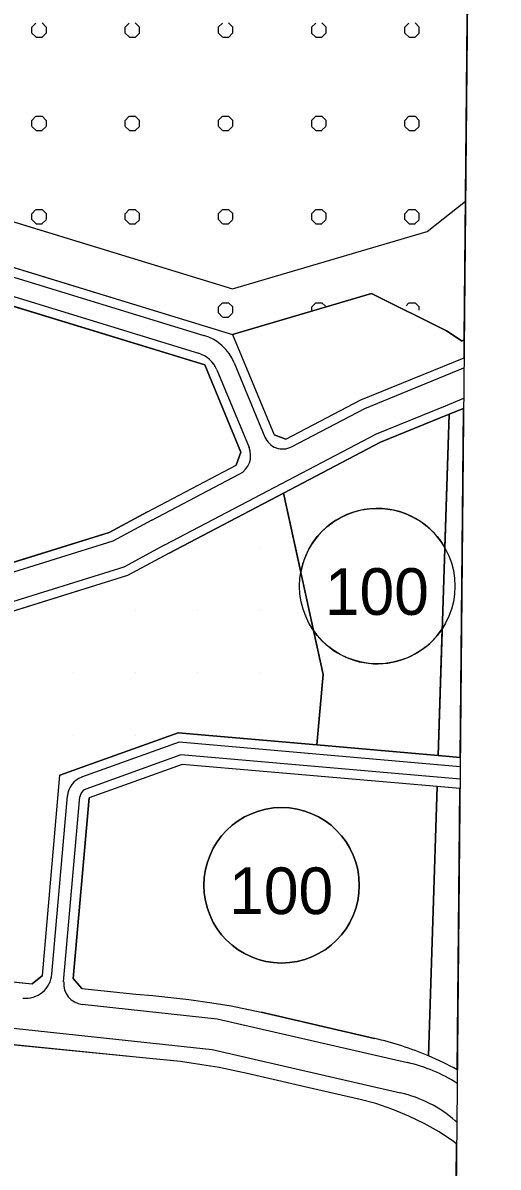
# Model space of a CAD drawing. Extents: x 427903 to 430077, y 4477233 to 4480385.
# Drawn here: x 429897.6 to 430050.5, y 4478600 to 4478968 of the extents above; entities that cross this region are included whole.
import ezdxf

# ---------------------------------------------------------------- set-up
doc = ezdxf.new("R2010")
doc.units = 0
for name, color, linetype in [('ADAKENARI', 7, 'Continuous'), ('KALDIRIM2', 7, 'Continuous'), ('PL_AYA_PARK_DINLENME', 7, 'Continuous'), ('PL_AYA_REKREASYON_AL', 7, 'Continuous'), ('PL_KA_TARIM_OZEL', 7, 'Continuous'), ('PL_KON_ONE_100', 7, 'Continuous'), ('PL_MESLEKI', 7, 'Continuous'), ('rezerv yapı alan', 7, 'Continuous'), ('SM_DAIRE', 7, 'Continuous'), ('SM_TAKS', 7, 'Continuous'), ('SıNıR', 7, 'Continuous'), ('TR_AZYOGUNKONUT', 7, 'Continuous'), ('TR_MESLEKTEKNİK', 7, 'Continuous'), ('TR_OZELMAHSUL', 7, 'Continuous')]:
    doc.layers.add(name, color=color, linetype=linetype)

msp = doc.modelspace()

# ---------------------------------------------------------------- linework, layer by layer
at = {"layer": 'ADAKENARI'}
for p, q in [((429779.96, 4478924.49), (429965.04, 4478867.84)), ((429778.16, 4478912.49), (429956.12, 4478858.02)), ((429965.04, 4478867.84), (430009.74, 4478881.03)), ((430009.74, 4478881.03), (430033.94, 4478869.02)), ((429965.04, 4478867.84), (429978.45, 4478835.49)), ((430033.94, 4478869.02), (430039, 4478865.62)), ((430039.62, 4478866.32), (430039, 4478865.62)), ((430006.33, 4478846.75), (430039.56, 4478860.29)), ((429956.12, 4478858.02), (429967.78, 4478829.9)), ((429982.26, 4478834.12), (430006.33, 4478846.75)), ((430034.72, 4478842.12), (430039.41, 4478844.03)), ((430012.66, 4478833.13), (430034.72, 4478842.12)), ((430034.72, 4478842.12), (430031.2, 4478732.4)), ((429982.26, 4478834.12), (429978.45, 4478835.49)), ((429981.49, 4478816.78), (430012.66, 4478833.13)), ((429967.78, 4478829.9), (429966.28, 4478825.73)), ((429937.68, 4478810.72), (429966.28, 4478825.73)), ((429944.72, 4478797.48), (429981.49, 4478816.78)), ((429994.21, 4478758.43), (429981.49, 4478816.78)), ((429937.68, 4478810.72), (429925.4, 4478804.12)), ((429925.4, 4478804.12), (429868.54, 4478786.43)), ((429944.71, 4478797.47), (429931.24, 4478790.23)), ((429931.24, 4478790.23), (429871.71, 4478771.71)), ((429994.21, 4478758.43), (429992.24, 4478735.79)), ((429947.54, 4478739.69), (429909.51, 4478726.04)), ((429992.24, 4478735.79), (429947.54, 4478739.69)), ((430031.2, 4478732.4), (429992.24, 4478735.79)), ((430038.34, 4478731.77), (430031.2, 4478732.4)), ((429903.89, 4478661.67), (429909.51, 4478726.04)), ((429948.86, 4478729.54), (429918.91, 4478718.79)), ((430030.88, 4478722.39), (429948.86, 4478729.54)), ((430030.88, 4478722.39), (430028.09, 4478635.77)), ((430038.24, 4478721.74), (430030.88, 4478722.39)), ((429913.85, 4478660.69), (429918.91, 4478718.79)), ((429810.6, 4478667.88), (429900.65, 4478658.98)), ((429903.89, 4478661.67), (429900.65, 4478658.98)), ((429916.57, 4478657.41), (429913.85, 4478660.69)), ((429916.57, 4478657.41), (429933.99, 4478655.68)), ((429933.99, 4478655.68), (429939.42, 4478655.15)), ((429939.42, 4478655.15), (429950.98, 4478653.96)), ((429950.98, 4478653.96), (429958.39, 4478652.85)), ((429958.39, 4478652.85), (429964.62, 4478651.87)), ((429964.62, 4478651.87), (429974.25, 4478649.82)), ((430010.75, 4478641.4), (429974.25, 4478649.82)), ((429937.24, 4478635.09), (429814.86, 4478647.18)), ((429948.29, 4478633.95), (429937.24, 4478635.09)), ((429955.17, 4478632.92), (429948.29, 4478633.95)), ((429960.8, 4478632.03), (429955.17, 4478632.92)), ((429969.74, 4478630.13), (429960.8, 4478632.03)), ((429992.56, 4478624.85), (429969.74, 4478630.13)), ((430006.15, 4478621.73), (429992.56, 4478624.85)), ((430011.13, 4478620.46), (430006.15, 4478621.73)), ((430016.67, 4478618.52), (430011.13, 4478620.46)), ((430021.78, 4478616.44), (430016.67, 4478618.52)), ((430026.71, 4478614.05), (430021.78, 4478616.44)), ((430031.6, 4478611.3), (430026.71, 4478614.05)), ((430036.22, 4478608.26), (430031.6, 4478611.3)), ((430037.15, 4478607.53), (430036.22, 4478608.26))]:
    msp.add_line(p, q, dxfattribs=at)
for start, end in [(67.0361, 77.0155), (61.3972, 67.0361)]:
    msp.add_arc((429987.2, 4478539.27), 104.81, start, end, dxfattribs=at)
at = {"layer": 'KALDIRIM2'}
for p, q in [((429790.01, 4478918.28), (429955.89, 4478867.5)), ((429788.25, 4478912.54), (429954.14, 4478861.76)), ((429965.58, 4478858.7), (429975.5, 4478834.79)), ((429960.03, 4478856.4), (429970.38, 4478831.48)), ((430007.6, 4478844.03), (430039.53, 4478857.04)), ((429984.08, 4478831.69), (430007.6, 4478844.03)), ((430011.4, 4478835.86), (430033.59, 4478844.9)), ((430033.59, 4478844.9), (430039.44, 4478847.28)), ((429978.73, 4478818.71), (430011.4, 4478835.86)), ((429939.09, 4478808.07), (429967.26, 4478822.86)), ((429943.32, 4478800.13), (429978.73, 4478818.71)), ((429939.09, 4478808.07), (429926.57, 4478801.34)), ((429926.57, 4478801.34), (429869.17, 4478783.49)), ((429943.29, 4478800.12), (429930.07, 4478793.01)), ((429930.07, 4478793.01), (429871.08, 4478774.65)), ((429947.94, 4478736.65), (429916.53, 4478725.37)), ((430038.31, 4478728.76), (429947.94, 4478736.65)), ((429948.47, 4478732.59), (429917.88, 4478721.61)), ((430038.27, 4478724.75), (429948.47, 4478732.59)), ((429906.94, 4478662.06), (429911.94, 4478719.42)), ((429910.74, 4478659.58), (429915.93, 4478719.07)), ((429816.04, 4478653.03), (429958.51, 4478637.85)), ((429816.04, 4478653.03), (429958.51, 4478637.85)), ((429916.69, 4478652.36), (429960.17, 4478647.73)), ((429960.17, 4478647.73), (430021.4, 4478633.61)), ((429958.51, 4478637.85), (430019.15, 4478623.87)), ((429958.51, 4478637.85), (430019.15, 4478623.87)), ((430037.22, 4478614.48), (430036.72, 4478614.91)), ((430037.22, 4478614.48), (430036.72, 4478614.91))]:
    msp.add_line(p, q, dxfattribs=at)
for centre, radius, start, end in [((429951.4, 4478852.82), 15.35, 22.5339, 72.9797), ((429951.4, 4478852.82), 9.35, 22.5339, 72.9797), ((429981.21, 4478837.16), 6.18, 202.5338, 297.6881), ((429964.1, 4478828.87), 6.8, 297.6881, 22.5338), ((429918.89, 4478718.81), 6.97, 109.747, 175.0148), ((429918.89, 4478718.81), 2.97, 109.747, 175.0148), ((429898.52, 4478662.8), 8.46, 263.9177, 355.0148), ((429917.4, 4478659), 6.68, 175.0148, 263.9177), ((430010.01, 4478584.22), 50.69, 57.3784, 77.019), ((430010.01, 4478584.22), 40.69, 48.9678, 77.019), ((430010.01, 4478584.22), 40.69, 48.9678, 77.019)]:
    msp.add_arc(centre, radius, start, end, dxfattribs=at)
at = {"layer": 'PL_AYA_PARK_DINLENME'}
for points in [[(430039.62, 4478866.32), (430039, 4478865.62), (430033.94, 4478869.02), (430009.74, 4478881.03), (429965.04, 4478867.84), (429978.45, 4478835.49), (429982.26, 4478834.12), (430006.33, 4478846.75), (430039.56, 4478860.29)], [(430039.56, 4478860.29), (430039.62, 4478866.32)], [(430039.41, 4478844.03), (430034.72, 4478842.12), (430031.2, 4478732.4), (430038.34, 4478731.77)], [(430038.34, 4478731.77), (430039.41, 4478844.03)], [(430038.24, 4478721.74), (430030.88, 4478722.39), (430028.09, 4478635.77)], [(430037.38, 4478631.29), (430038.24, 4478721.74)]]:
    msp.add_lwpolyline(points, dxfattribs=at)
msp.add_arc((429987.2, 4478539.27), 104.81, 61.3973, 67.0361, dxfattribs=at)
at = {"layer": 'PL_AYA_REKREASYON_AL'}
for points in [[(430037.15, 4478607.53), (430036.22, 4478608.26), (430031.6, 4478611.3), (430026.71, 4478614.05), (430021.78, 4478616.44), (430016.67, 4478618.52), (430011.13, 4478620.46), (430006.15, 4478621.73), (429992.56, 4478624.85), (429969.74, 4478630.13), (429960.8, 4478632.03), (429955.17, 4478632.92), (429948.29, 4478633.95), (429937.24, 4478635.09), (429814.86, 4478647.18), (429808.17, 4478641.82), (429802.69, 4478596.3)], [(430035.95, 4478482.02), (430037.15, 4478607.53)]]:
    msp.add_lwpolyline(points, dxfattribs=at)
at = {"layer": 'PL_KA_TARIM_OZEL'}
for points in [[(430039.62, 4478866.32), (430041.04, 4479015.36)], [(429185.17, 4478965.6), (429186.08, 4478965.07), (429221.81, 4478944.56), (429259.98, 4478922.84), (429299.06, 4478900.66), (429338.45, 4478878.32), (429344.42, 4478874.94), (429379.33, 4478881.11), (429380.15, 4478898.3), (429392.14, 4478897.73), (429391.78, 4478890.33), (429396.47, 4478886.21), (429613.09, 4478924.65), (429779.96, 4478924.49), (429965.04, 4478867.84), (430009.74, 4478881.03), (430033.94, 4478869.02), (430039, 4478865.62), (430039.62, 4478866.32)]]:
    msp.add_lwpolyline(points, dxfattribs=at)
at = {"layer": 'PL_KON_ONE_100'}
for points in [[(429703.83, 4478785.08), (429809.52, 4478788.03), (429859.15, 4478785.27), (429868.54, 4478786.43), (429925.4, 4478804.12), (429937.68, 4478810.72), (429966.28, 4478825.73), (429967.78, 4478829.9), (429956.12, 4478858.02), (429778.16, 4478912.49), (429642.39, 4478912.63)], [(430031.2, 4478732.4), (430034.72, 4478842.12), (430012.66, 4478833.13), (429981.49, 4478816.78), (429994.21, 4478758.43), (429992.24, 4478735.79), (430031.2, 4478732.4)], [(430028.09, 4478635.77), (430030.88, 4478722.39), (429948.86, 4478729.54), (429918.91, 4478718.79), (429913.85, 4478660.69), (429916.57, 4478657.41), (429933.99, 4478655.68), (429939.42, 4478655.15), (429950.98, 4478653.96), (429958.39, 4478652.85), (429964.62, 4478651.87), (429974.25, 4478649.82), (430010.75, 4478641.4)]]:
    msp.add_lwpolyline(points, dxfattribs=at)
msp.add_arc((429987.2, 4478539.27), 104.81, 67.0361, 77.0155, dxfattribs=at)
at = {"layer": 'PL_MESLEKI'}
msp.add_lwpolyline([(429991.12, 4478772.6), (429987.04, 4478791.33), (429981.49, 4478816.78), (429944.71, 4478797.47), (429931.24, 4478790.23), (429871.71, 4478771.71), (429859.66, 4478770.22), (429809.16, 4478773.03), (429741.71, 4478771.14), (429742.27, 4478751.03), (429673.79, 4478725.23), (429753.01, 4478675.43), (429790.96, 4478670.46), (429810.6, 4478667.88), (429900.65, 4478658.98), (429903.89, 4478661.67), (429909.51, 4478726.04), (429947.54, 4478739.69), (429992.24, 4478735.79), (429994.21, 4478758.43), (429991.12, 4478772.6)], dxfattribs=at)
at = {"layer": 'rezerv yapı alan'}
for p, q in [((429782.06, 4478938.49), (429965.11, 4478882.46)), ((430027.68, 4478900.91), (430040.04, 4478910.67)), ((429965.11, 4478882.46), (430027.68, 4478900.91))]:
    msp.add_line(p, q, dxfattribs=at)
for points in [[(430040.04, 4478910.67), (430050.52, 4480009.82), (427929.02, 4480028.95), (427921.98, 4479290.57)], [(427921.98, 4479290.57), (427971.55, 4479260.72), (427987.38, 4479256.4), (428128.47, 4479257.63), (428368.56, 4479183.35), (428552.54, 4479194.57), (428656.99, 4479201.54), (428694.28, 4479196.96), (428778.69, 4479177.41), (428853.9, 4479147.32), (428942.46, 4479108.55), (429057.71, 4479108.55), (429083.4, 4479100.66), (429102.93, 4479079.75), (429129.55, 4479022.57), (429151, 4479001.12), (429217.97, 4478963.3), (429343.9, 4478891.1), (429611.87, 4478938.66), (429782.06, 4478938.49), (429965.11, 4478882.46), (430027.68, 4478900.91), (430040.04, 4478910.67)]]:
    msp.add_lwpolyline(points, dxfattribs=at)
at = {"layer": 'SM_DAIRE'}
for centre in [(430011.64, 4478786.88), (429980.86, 4478690.64)]:
    msp.add_circle(centre, 25, dxfattribs=at)
at = {"layer": 'SıNıR'}
msp.add_line((430050.52, 4480009.82), (430024.04, 4477233.04), dxfattribs=at)
at = {"layer": 'TR_AZYOGUNKONUT'}
for points in [[(429956.12, 4478858.02), (429778.16, 4478912.49), (429642.39, 4478912.63), (429660.09, 4478771.16)], [(429703.83, 4478785.08), (429809.52, 4478788.03), (429859.15, 4478785.27), (429868.54, 4478786.43), (429925.4, 4478804.12), (429937.68, 4478810.72), (429966.28, 4478825.73), (429967.78, 4478829.9), (429956.12, 4478858.02)], [(430033.35, 4478799.29), (430034.72, 4478842.12), (430012.66, 4478833.13), (429981.49, 4478816.78), (429987.04, 4478791.33)], [(429991.12, 4478772.6), (429994.21, 4478758.43), (429992.24, 4478735.79), (430031.2, 4478732.4), (430032.5, 4478773.1)], [(430028.09, 4478635.77), (430030.88, 4478722.39), (429948.86, 4478729.54), (429918.91, 4478718.79), (429913.85, 4478660.69), (429916.57, 4478657.41), (429933.99, 4478655.68), (429939.42, 4478655.15), (429950.98, 4478653.96), (429958.39, 4478652.85), (429964.62, 4478651.87), (429974.25, 4478649.82), (430010.75, 4478641.4)]]:
    msp.add_lwpolyline(points, dxfattribs=at)
for centre, radius, start, end in [((430011.64, 4478786.88), 25, 29.7639, 169.754), ((430011.64, 4478786.88), 25, 214.8391, 326.5565), ((429980.86, 4478690.64), 25, 0, 180), ((429980.86, 4478690.64), 25, 180, 0), ((429987.2, 4478539.27), 104.81, 77.0149, 77.0155), ((429987.2, 4478539.27), 104.81, 67.0361, 77.015)]:
    msp.add_arc(centre, radius, start, end, dxfattribs=at)
at = {"layer": 'TR_MESLEKTEKNİK'}
for p, q in [((429953.79, 4478798.98), (429953.79, 4478798.98)), ((429973.79, 4478798.98), (429973.79, 4478798.98)), ((429933.79, 4478778.98), (429933.79, 4478778.98)), ((429953.79, 4478778.98), (429953.79, 4478778.98)), ((429973.79, 4478778.98), (429973.79, 4478778.98)), ((429913.79, 4478758.98), (429913.79, 4478758.98)), ((429933.79, 4478758.98), (429933.79, 4478758.98)), ((429953.79, 4478758.98), (429953.79, 4478758.98)), ((429973.79, 4478758.98), (429973.79, 4478758.98)), ((429913.79, 4478738.98), (429913.79, 4478738.98)), ((429933.79, 4478738.98), (429933.79, 4478738.98)), ((429973.79, 4478738.98), (429973.79, 4478738.98))]:
    msp.add_line(p, q, dxfattribs=at)
at = {"layer": 'TR_OZELMAHSUL'}
for p, q in [((429900.49, 4478966.62), (429901.84, 4478967.97)), ((429900.54, 4478964.75), (429900.54, 4478966.66)), ((429905.16, 4478966.66), (429903.8, 4478968.01)), ((429905.17, 4478964.75), (429905.17, 4478966.66)), ((429930.49, 4478966.62), (429931.84, 4478967.97)), ((429930.54, 4478964.75), (429930.54, 4478966.66)), ((429935.16, 4478966.66), (429933.8, 4478968.01)), ((429935.17, 4478964.75), (429935.17, 4478966.66)), ((429960.48, 4478966.62), (429961.84, 4478967.97)), ((429960.54, 4478964.75), (429960.54, 4478966.66)), ((429965.16, 4478966.66), (429963.8, 4478968.01)), ((429965.17, 4478964.75), (429965.17, 4478966.66)), ((429990.48, 4478966.62), (429991.84, 4478967.97)), ((429990.54, 4478964.75), (429990.54, 4478966.66)), ((429995.15, 4478966.66), (429993.8, 4478968.01)), ((429995.17, 4478964.75), (429995.17, 4478966.66)), ((430020.48, 4478966.62), (430021.84, 4478967.97)), ((430020.54, 4478964.75), (430020.54, 4478966.66)), ((430025.15, 4478966.66), (430023.8, 4478968.01)), ((430025.17, 4478964.75), (430025.17, 4478966.66)), ((429901.89, 4478963.39), (429900.53, 4478964.74)), ((429901.9, 4478963.39), (429903.82, 4478963.39)), ((429903.76, 4478963.35), (429905.11, 4478964.7)), ((429931.89, 4478963.39), (429930.53, 4478964.74)), ((429931.9, 4478963.39), (429933.82, 4478963.39)), ((429933.76, 4478963.35), (429935.11, 4478964.7)), ((429961.89, 4478963.39), (429960.53, 4478964.74)), ((429961.9, 4478963.39), (429963.82, 4478963.39)), ((429963.75, 4478963.35), (429965.11, 4478964.7)), ((429991.88, 4478963.39), (429990.53, 4478964.74)), ((429991.9, 4478963.39), (429993.82, 4478963.39)), ((429993.75, 4478963.35), (429995.11, 4478964.7)), ((430021.88, 4478963.39), (430020.53, 4478964.74)), ((430021.9, 4478963.39), (430023.82, 4478963.39)), ((430023.75, 4478963.35), (430025.11, 4478964.7)), ((429900.49, 4478936.62), (429901.84, 4478937.97)), ((429900.54, 4478934.75), (429900.54, 4478936.66)), ((429901.9, 4478938.02), (429903.82, 4478938.02)), ((429905.16, 4478936.66), (429903.8, 4478938.01)), ((429905.17, 4478934.75), (429905.17, 4478936.66)), ((429930.49, 4478936.62), (429931.84, 4478937.97)), ((429930.54, 4478934.75), (429930.54, 4478936.66)), ((429931.9, 4478938.02), (429933.82, 4478938.02)), ((429935.15, 4478936.66), (429933.8, 4478938.01)), ((429935.17, 4478934.75), (429935.17, 4478936.66)), ((429960.48, 4478936.62), (429961.84, 4478937.97)), ((429960.54, 4478934.75), (429960.54, 4478936.66)), ((429961.9, 4478938.02), (429963.82, 4478938.02)), ((429965.15, 4478936.66), (429963.8, 4478938.01)), ((429965.17, 4478934.75), (429965.17, 4478936.66)), ((429990.48, 4478936.62), (429991.84, 4478937.97)), ((429990.54, 4478934.75), (429990.54, 4478936.66)), ((429991.9, 4478938.02), (429993.82, 4478938.02)), ((429995.15, 4478936.66), (429993.8, 4478938.01)), ((429995.17, 4478934.75), (429995.17, 4478936.66)), ((430020.48, 4478936.62), (430021.84, 4478937.97)), ((430020.54, 4478934.75), (430020.54, 4478936.66)), ((430021.9, 4478938.02), (430023.82, 4478938.02)), ((430025.15, 4478936.66), (430023.8, 4478938.01)), ((430025.17, 4478934.75), (430025.17, 4478936.66)), ((429901.89, 4478933.39), (429900.53, 4478934.74)), ((429901.9, 4478933.39), (429903.82, 4478933.39)), ((429903.76, 4478933.35), (429905.11, 4478934.7)), ((429931.88, 4478933.39), (429930.53, 4478934.74)), ((429931.9, 4478933.39), (429933.82, 4478933.39)), ((429933.76, 4478933.35), (429935.11, 4478934.7)), ((429961.88, 4478933.39), (429960.53, 4478934.74)), ((429961.9, 4478933.39), (429963.82, 4478933.39)), ((429963.75, 4478933.35), (429965.11, 4478934.7)), ((429991.88, 4478933.39), (429990.53, 4478934.74)), ((429991.9, 4478933.39), (429993.82, 4478933.39)), ((429993.75, 4478933.35), (429995.11, 4478934.7)), ((430021.88, 4478933.39), (430020.53, 4478934.74)), ((430021.9, 4478933.39), (430023.82, 4478933.39)), ((430023.75, 4478933.35), (430025.11, 4478934.7)), ((429900.49, 4478906.62), (429901.84, 4478907.97)), ((429900.54, 4478904.75), (429900.54, 4478906.66)), ((429901.9, 4478908.02), (429903.82, 4478908.02)), ((429905.15, 4478906.66), (429903.8, 4478908.01)), ((429905.17, 4478904.75), (429905.17, 4478906.66)), ((429930.49, 4478906.62), (429931.84, 4478907.97)), ((429930.54, 4478904.75), (429930.54, 4478906.66)), ((429931.9, 4478908.02), (429933.82, 4478908.02)), ((429935.15, 4478906.66), (429933.8, 4478908.01)), ((429935.17, 4478904.75), (429935.17, 4478906.66)), ((429960.48, 4478906.62), (429961.84, 4478907.97)), ((429960.54, 4478904.75), (429960.54, 4478906.66)), ((429961.9, 4478908.02), (429963.82, 4478908.02)), ((429965.15, 4478906.66), (429963.8, 4478908.01)), ((429965.17, 4478904.75), (429965.17, 4478906.66)), ((429990.48, 4478906.62), (429991.84, 4478907.97)), ((429990.54, 4478904.75), (429990.54, 4478906.66)), ((429991.9, 4478908.02), (429993.82, 4478908.02)), ((429995.15, 4478906.66), (429993.8, 4478908.01)), ((429995.17, 4478904.75), (429995.17, 4478906.66)), ((430020.48, 4478906.62), (430021.84, 4478907.97)), ((430020.54, 4478904.75), (430020.54, 4478906.66)), ((430021.9, 4478908.02), (430023.82, 4478908.02)), ((430025.15, 4478906.66), (430023.8, 4478908.01)), ((430025.17, 4478904.75), (430025.17, 4478906.66)), ((429901.88, 4478903.39), (429900.53, 4478904.74)), ((429901.9, 4478903.39), (429903.82, 4478903.39)), ((429903.76, 4478903.35), (429905.11, 4478904.7)), ((429931.88, 4478903.39), (429930.53, 4478904.74)), ((429931.9, 4478903.39), (429933.82, 4478903.39)), ((429933.76, 4478903.35), (429935.11, 4478904.7)), ((429961.88, 4478903.39), (429960.53, 4478904.74)), ((429961.9, 4478903.39), (429963.82, 4478903.39)), ((429963.75, 4478903.35), (429965.11, 4478904.7)), ((429991.88, 4478903.39), (429990.53, 4478904.74)), ((429991.9, 4478903.39), (429993.82, 4478903.39)), ((429993.75, 4478903.35), (429995.11, 4478904.7)), ((430021.88, 4478903.39), (430020.53, 4478904.74)), ((430021.9, 4478903.39), (430023.82, 4478903.39)), ((430023.75, 4478903.35), (430025.11, 4478904.7)), ((429960.48, 4478876.62), (429961.84, 4478877.97)), ((429961.9, 4478878.02), (429963.82, 4478878.02)), ((429965.15, 4478876.66), (429963.8, 4478878.02)), ((429990.48, 4478876.62), (429991.84, 4478877.97)), ((429991.9, 4478878.02), (429993.82, 4478878.02)), ((429994.94, 4478876.87), (429993.8, 4478878.02)), ((430020.89, 4478877.03), (430021.84, 4478877.97)), ((430021.9, 4478878.02), (430023.82, 4478878.02)), ((430021.9, 4478878.02), (430023.82, 4478878.02)), ((430025.15, 4478876.66), (430023.8, 4478878.02)), ((429961.88, 4478873.39), (429960.53, 4478874.75)), ((429960.54, 4478874.75), (429960.54, 4478876.66)), ((429961.9, 4478873.39), (429963.82, 4478873.39)), ((429963.75, 4478873.35), (429965.11, 4478874.7)), ((429965.17, 4478874.75), (429965.17, 4478876.66)), ((429990.54, 4478875.64), (429990.54, 4478876.66)), ((430025.17, 4478875.6), (430025.17, 4478876.66))]:
    msp.add_line(p, q, dxfattribs=at)

# ---------------------------------------------------------------- texts
at = {"layer": 'SM_TAKS'}
for p in [(429994.78, 4478777.62), (429963.99, 4478681.38)]:
    msp.add_text('100', height=15, dxfattribs=at).set_placement(p)

doc.saveas('drawing.dxf')
